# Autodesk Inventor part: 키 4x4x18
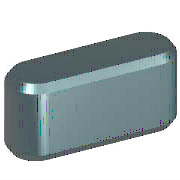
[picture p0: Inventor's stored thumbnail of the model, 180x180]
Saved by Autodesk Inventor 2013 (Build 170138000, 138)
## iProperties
IsCustomPart: 1
Created: 2012-02
Part Number: 키 4x4x18
Material: 강철, 연강
Description: 키 및 해당 키홈
Document SubType Name: Modeling
Standard: KS B 1311
Designer: mduedu
Standards Organization: KS
Language: ko-KR
Size Designation: 4 x 4 x 18
Categories: <MemberInstance><Categories><Category DisplayName="샤프트 부품" InternalName="7f7aeb1f-a693-4053-b835-cee3144e0d98" Mnemonic="SHFT"><Category DisplayName="키" Interna
Density: 7.86 g/cm^3
Mass: 2.13606 g
Surface Area: 2.87354 cm^2
Volume: 0.271763 cm^3
Author: mduedu
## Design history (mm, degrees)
workplane "Work Plane1"
workplane "Work Plane2"
sketch "스케치1"
  geometry: L1 (2, 2)-(16, 2); L2 (16, -2)-(2, -2); L3 (0, 9.4)-(0, -7.4) reference; L4 (-5, 0)-(30, 0) reference; L5 (18, 0)-(18, 7); A1 r 2 centre (2, 0) between (2, 2) and (2, -2); A2 r 2 centre (16, 0) between (16, -2) and (16, 2)
  constraints: 6 end point, 5 point on circle, 4 tangent, 3 point on line, 2 centre point, 1 horizontal, 1 parallel, 1 perpendicular
  dimensions: "d0" = 2 radius of A1 (= 0.5 x PB); "d13" = 2 radius of A2 (= 0.5 x PB); "d14" = 18 distance between parallel lines of L5 L3 (= NLG)
extrude "본체1" new body sketch "스케치1" taper "d3" = 0 deg; stored distance "d4" = 10
workplane "Work Plane3"
body "Solid1"
chamfer "모따기1" distance "d8" = 0.25 (= PHH); stored, may be unused: second distance "d9" = 0.25 (= PHH), angle "d15" = 45 deg
other parameters: "d1" = -2.5 (= -PNT), "d2" = 1.5 (= PH - PNT), "NLG" = 18 [user parameter; used in 3 equation terms], "PB" = 4 [user parameter; used in 2 equation terms], "PNT" = 2.5 [user parameter; used in 2 equation terms], "PH" = 4 [user parameter; used in 1 equation term], "PHH" = 0.25 [user parameter; used in 2 equation terms], "d10" = 0, "d16" = 0, "d17" = 0, "d18" = 0, "PLB2" = 18 (= NLG) [user parameter], "WDMAX" = 12 [user parameter], "PLB1" = 18 (= NLG) [user parameter], "RR" = 0.08 [user parameter], "PUEB" = 1.8 [user parameter]
